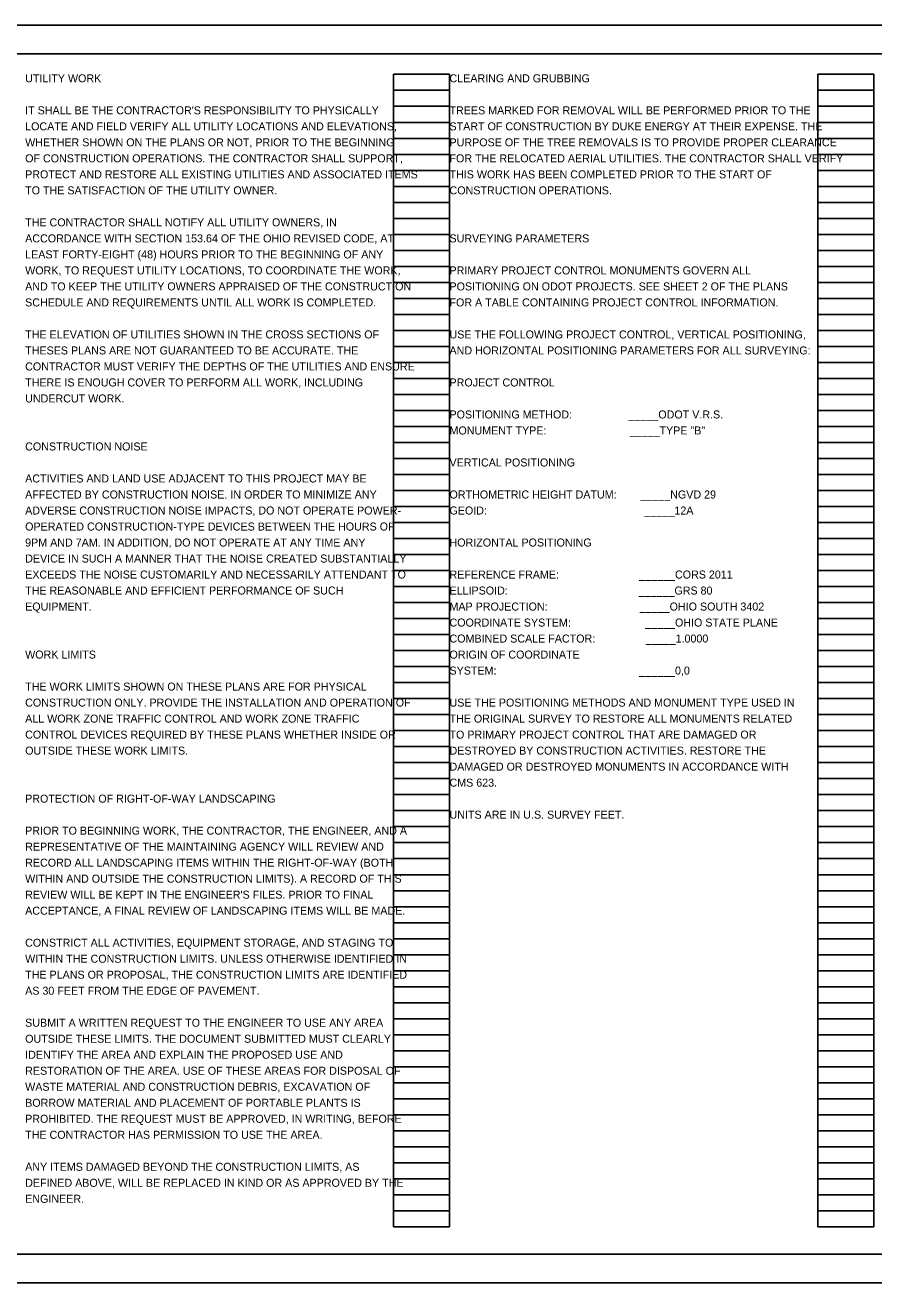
# Model space of a CAD drawing. Extents: x 0 to 50.1, y 0 to 22.
# Drawn here: x 9.82 to 24.66, y 0 to 22 of the extents above; entities that cross this region are included whole.
import ezdxf

# ---------------------------------------------------------------- set-up
doc = ezdxf.new("R2010")
doc.units = 0
for name, color, linetype in [('SH_Border', 7, 'Continuous'), ('SH_Cut_Line', 7, 'Continuous'), ('SH_Data', 7, 'Continuous'), ('SH_Text', 7, 'Continuous')]:
    doc.layers.add(name, color=color, linetype=linetype)

msp = doc.modelspace()

# ---------------------------------------------------------------- linework, layer by layer
at = {"layer": 'SH_Border'}
msp.add_lwpolyline([(1.5, 21.5), (33.5, 21.5), (33.5, 0.5), (1.5, 0.5)], close=True, dxfattribs=at)
at = {"layer": 'SH_Cut_Line'}
msp.add_lwpolyline([(0, 0), (34, 0), (34, 22), (0, 22)], close=True, dxfattribs=at)
at = {"layer": 'SH_Data'}
for p, q in [((16.26, 0.98), (16.26, 21.14)), ((16.26, 21.14), (17.24, 21.14)), ((17.24, 0.98), (17.24, 21.14)), ((23.68, 0.98), (23.68, 21.14)), ((23.68, 21.14), (24.66, 21.14)), ((24.66, 0.98), (24.66, 21.14)), ((16.26, 20.86), (17.24, 20.86)), ((23.68, 20.86), (24.66, 20.86)), ((16.26, 20.58), (17.24, 20.58)), ((23.68, 20.58), (24.66, 20.58)), ((16.26, 20.3), (17.24, 20.3)), ((23.68, 20.3), (24.66, 20.3)), ((16.26, 20.02), (17.24, 20.02)), ((23.68, 20.02), (24.66, 20.02)), ((16.26, 19.74), (17.24, 19.74)), ((23.68, 19.74), (24.66, 19.74)), ((16.26, 19.46), (17.24, 19.46)), ((23.68, 19.46), (24.66, 19.46)), ((16.26, 19.18), (17.24, 19.18)), ((23.68, 19.18), (24.66, 19.18)), ((16.26, 18.9), (17.24, 18.9)), ((23.68, 18.9), (24.66, 18.9)), ((16.26, 18.62), (17.24, 18.62)), ((23.68, 18.62), (24.66, 18.62)), ((16.26, 18.34), (17.24, 18.34)), ((23.68, 18.34), (24.66, 18.34)), ((16.26, 18.06), (17.24, 18.06)), ((23.68, 18.06), (24.66, 18.06)), ((16.26, 17.78), (17.24, 17.78)), ((23.68, 17.78), (24.66, 17.78)), ((16.26, 17.5), (17.24, 17.5)), ((23.68, 17.5), (24.66, 17.5)), ((16.26, 17.22), (17.24, 17.22)), ((23.68, 17.22), (24.66, 17.22)), ((16.26, 16.94), (17.24, 16.94)), ((23.68, 16.94), (24.66, 16.94)), ((16.26, 16.66), (17.24, 16.66)), ((23.68, 16.66), (24.66, 16.66)), ((16.26, 16.38), (17.24, 16.38)), ((23.68, 16.38), (24.66, 16.38)), ((16.26, 16.1), (17.24, 16.1)), ((23.68, 16.1), (24.66, 16.1)), ((16.26, 15.82), (17.24, 15.82)), ((23.68, 15.82), (24.66, 15.82)), ((16.26, 15.54), (17.24, 15.54)), ((23.68, 15.54), (24.66, 15.54)), ((16.26, 15.26), (17.24, 15.26)), ((23.68, 15.26), (24.66, 15.26)), ((16.26, 14.98), (17.24, 14.98)), ((23.68, 14.98), (24.66, 14.98)), ((16.26, 14.7), (17.24, 14.7)), ((23.68, 14.7), (24.66, 14.7)), ((16.26, 14.42), (17.24, 14.42)), ((23.68, 14.42), (24.66, 14.42)), ((16.26, 14.14), (17.24, 14.14)), ((23.68, 14.14), (24.66, 14.14)), ((16.26, 13.86), (17.24, 13.86)), ((23.68, 13.86), (24.66, 13.86)), ((16.26, 13.58), (17.24, 13.58)), ((23.68, 13.58), (24.66, 13.58)), ((16.26, 13.3), (17.24, 13.3)), ((23.68, 13.3), (24.66, 13.3)), ((16.26, 13.02), (17.24, 13.02)), ((23.68, 13.02), (24.66, 13.02)), ((16.26, 12.74), (17.24, 12.74)), ((23.68, 12.74), (24.66, 12.74)), ((16.26, 12.46), (17.24, 12.46)), ((23.68, 12.46), (24.66, 12.46)), ((16.26, 12.18), (17.24, 12.18)), ((23.68, 12.18), (24.66, 12.18)), ((16.26, 11.9), (17.24, 11.9)), ((23.68, 11.9), (24.66, 11.9)), ((16.26, 11.62), (17.24, 11.62)), ((23.68, 11.62), (24.66, 11.62)), ((16.26, 11.34), (17.24, 11.34)), ((23.68, 11.34), (24.66, 11.34)), ((16.26, 11.06), (17.24, 11.06)), ((23.68, 11.06), (24.66, 11.06)), ((16.26, 10.78), (17.24, 10.78)), ((23.68, 10.78), (24.66, 10.78)), ((16.26, 10.5), (17.24, 10.5)), ((23.68, 10.5), (24.66, 10.5)), ((16.26, 10.22), (17.24, 10.22)), ((23.68, 10.22), (24.66, 10.22)), ((16.26, 9.94), (17.24, 9.94)), ((23.68, 9.94), (24.66, 9.94)), ((16.26, 9.66), (17.24, 9.66)), ((23.68, 9.66), (24.66, 9.66)), ((16.26, 9.38), (17.24, 9.38)), ((23.68, 9.38), (24.66, 9.38)), ((16.26, 9.1), (17.24, 9.1)), ((23.68, 9.1), (24.66, 9.1)), ((16.26, 8.82), (17.24, 8.82)), ((23.68, 8.82), (24.66, 8.82)), ((16.26, 8.54), (17.24, 8.54)), ((23.68, 8.54), (24.66, 8.54)), ((16.26, 8.26), (17.24, 8.26)), ((23.68, 8.26), (24.66, 8.26)), ((16.26, 7.98), (17.24, 7.98)), ((23.68, 7.98), (24.66, 7.98)), ((16.26, 7.7), (17.24, 7.7)), ((23.68, 7.7), (24.66, 7.7)), ((16.26, 7.42), (17.24, 7.42)), ((23.68, 7.42), (24.66, 7.42)), ((16.26, 7.14), (17.24, 7.14)), ((23.68, 7.14), (24.66, 7.14)), ((16.26, 6.86), (17.24, 6.86)), ((23.68, 6.86), (24.66, 6.86)), ((16.26, 6.58), (17.24, 6.58)), ((23.68, 6.58), (24.66, 6.58)), ((16.26, 6.3), (17.24, 6.3)), ((23.68, 6.3), (24.66, 6.3)), ((16.26, 6.02), (17.24, 6.02)), ((23.68, 6.02), (24.66, 6.02)), ((16.26, 5.74), (17.24, 5.74)), ((23.68, 5.74), (24.66, 5.74)), ((16.26, 5.46), (17.24, 5.46)), ((23.68, 5.46), (24.66, 5.46)), ((16.26, 5.18), (17.24, 5.18)), ((23.68, 5.18), (24.66, 5.18)), ((16.26, 4.9), (17.24, 4.9)), ((23.68, 4.9), (24.66, 4.9)), ((16.26, 4.62), (17.24, 4.62)), ((23.68, 4.62), (24.66, 4.62)), ((16.26, 4.34), (17.24, 4.34)), ((23.68, 4.34), (24.66, 4.34)), ((16.26, 4.06), (17.24, 4.06)), ((23.68, 4.06), (24.66, 4.06)), ((16.26, 3.78), (17.24, 3.78)), ((23.68, 3.78), (24.66, 3.78)), ((16.26, 3.5), (17.24, 3.5)), ((23.68, 3.5), (24.66, 3.5)), ((16.26, 3.22), (17.24, 3.22)), ((23.68, 3.22), (24.66, 3.22)), ((16.26, 2.94), (17.24, 2.94)), ((23.68, 2.94), (24.66, 2.94)), ((16.26, 2.66), (17.24, 2.66)), ((23.68, 2.66), (24.66, 2.66)), ((16.26, 2.38), (17.24, 2.38)), ((23.68, 2.38), (24.66, 2.38)), ((16.26, 2.1), (17.24, 2.1)), ((23.68, 2.1), (24.66, 2.1)), ((16.26, 1.82), (17.24, 1.82)), ((23.68, 1.82), (24.66, 1.82)), ((16.26, 1.54), (17.24, 1.54)), ((23.68, 1.54), (24.66, 1.54)), ((16.26, 1.26), (17.24, 1.26)), ((23.68, 1.26), (24.66, 1.26)), ((16.26, 0.98), (17.24, 0.98)), ((23.68, 0.98), (24.66, 0.98))]:
    msp.add_line(p, q, dxfattribs=at)

# ---------------------------------------------------------------- texts
at = {"layer": 'SH_Text'}
for s, p in [('UTILITY WORK', (9.82, 21)), ('CLEARING AND GRUBBING', (17.24, 21)), ("IT SHALL BE THE CONTRACTOR'S RESPONSIBILITY TO PHYSICALLY ", (9.82, 20.44)), ('TREES MARKED FOR REMOVAL WILL BE PERFORMED PRIOR TO THE ', (17.24, 20.44)), ('LOCATE AND FIELD VERIFY ALL UTILITY LOCATIONS AND ELEVATIONS, ', (9.82, 20.16)), ('START OF CONSTRUCTION BY DUKE ENERGY AT THEIR EXPENSE. THE ', (17.24, 20.16)), ('WHETHER SHOWN ON THE PLANS OR NOT, PRIOR TO THE BEGINNING ', (9.82, 19.88)), ('PURPOSE OF THE TREE REMOVALS IS TO PROVIDE PROPER CLEARANCE ', (17.24, 19.88)), ('OF CONSTRUCTION OPERATIONS. THE CONTRACTOR SHALL SUPPORT, ', (9.82, 19.6)), ('FOR THE RELOCATED AERIAL UTILITIES. THE CONTRACTOR SHALL VERIFY ', (17.24, 19.6)), ('PROTECT AND RESTORE ALL EXISTING UTILITIES AND ASSOCIATED ITEMS ', (9.82, 19.32)), ('THIS WORK HAS BEEN COMPLETED PRIOR TO THE START OF ', (17.24, 19.32)), ('TO THE SATISFACTION OF THE UTILITY OWNER. ', (9.82, 19.04)), ('CONSTRUCTION OPERATIONS. ', (17.24, 19.04)), ('THE CONTRACTOR SHALL NOTIFY ALL UTILITY OWNERS, IN ', (9.82, 18.48)), ('ACCORDANCE WITH SECTION 153.64 OF THE OHIO REVISED CODE, AT ', (9.82, 18.2)), ('SURVEYING PARAMETERS', (17.24, 18.2)), ('LEAST FORTY-EIGHT (48) HOURS PRIOR TO THE BEGINNING OF ANY ', (9.82, 17.92)), ('WORK, TO REQUEST UTILITY LOCATIONS, TO COORDINATE THE WORK, ', (9.82, 17.64)), ('PRIMARY PROJECT CONTROL MONUMENTS GOVERN ALL', (17.24, 17.64)), ('AND TO KEEP THE UTILITY OWNERS APPRAISED OF THE CONSTRUCTION ', (9.82, 17.36)), ('POSITIONING ON ODOT PROJECTS. SEE SHEET 2 OF THE PLANS', (17.24, 17.36)), ('SCHEDULE AND REQUIREMENTS UNTIL ALL WORK IS COMPLETED. ', (9.82, 17.08)), ('FOR A TABLE CONTAINING PROJECT CONTROL INFORMATION.', (17.24, 17.08)), ('THE ELEVATION OF UTILITIES SHOWN IN THE CROSS SECTIONS OF ', (9.82, 16.52)), ('USE THE FOLLOWING PROJECT CONTROL, VERTICAL POSITIONING,', (17.24, 16.52)), ('THESES PLANS ARE NOT GUARANTEED TO BE ACCURATE. THE ', (9.82, 16.24)), ('AND HORIZONTAL POSITIONING PARAMETERS FOR ALL SURVEYING:', (17.24, 16.24)), ('CONTRACTOR MUST VERIFY THE DEPTHS OF THE UTILITIES AND ENSURE ', (9.82, 15.96)), ('THERE IS ENOUGH COVER TO PERFORM ALL WORK, INCLUDING ', (9.82, 15.68)), ('PROJECT CONTROL', (17.24, 15.68)), ('UNDERCUT WORK.', (9.82, 15.4)), ('POSITIONING METHOD:                   _____ODOT V.R.S.', (17.24, 15.12)), ('MONUMENT TYPE:                            _____TYPE "B"', (17.24, 14.84)), ('CONSTRUCTION NOISE', (9.82, 14.56)), ('VERTICAL POSITIONING', (17.24, 14.28)), ('ACTIVITIES AND LAND USE ADJACENT TO THIS PROJECT MAY BE ', (9.82, 14)), ('AFFECTED BY CONSTRUCTION NOISE. IN ORDER TO MINIMIZE ANY ', (9.82, 13.72)), ('ORTHOMETRIC HEIGHT DATUM:        _____NGVD 29', (17.24, 13.72)), ('ADVERSE CONSTRUCTION NOISE IMPACTS, DO NOT OPERATE POWER-', (9.82, 13.44)), ('GEOID:                                                     _____12A', (17.24, 13.44)), ('OPERATED CONSTRUCTION-TYPE DEVICES BETWEEN THE HOURS OF ', (9.82, 13.16)), ('9PM AND 7AM. IN ADDITION, DO NOT OPERATE AT ANY TIME ANY ', (9.82, 12.88)), ('HORIZONTAL POSITIONING', (17.24, 12.88)), ('DEVICE IN SUCH A MANNER THAT THE NOISE CREATED SUBSTANTIALLY ', (9.82, 12.6)), ('EXCEEDS THE NOISE CUSTOMARILY AND NECESSARILY ATTENDANT TO ', (9.82, 12.32)), ('REFERENCE FRAME:                           ______CORS 2011', (17.24, 12.32)), ('THE REASONABLE AND EFFICIENT PERFORMANCE OF SUCH ', (9.82, 12.04)), ('ELLIPSOID:                                            ______GRS 80', (17.24, 12.04)), ('EQUIPMENT.', (9.82, 11.76)), ('MAP PROJECTION:                               _____OHIO SOUTH 3402', (17.24, 11.76)), ('COORDINATE SYSTEM:                         _____OHIO STATE PLANE', (17.24, 11.48)), ('COMBINED SCALE FACTOR:                 _____1.0000', (17.24, 11.2)), ('WORK LIMITS', (9.82, 10.92)), ('ORIGIN OF COORDINATE', (17.24, 10.92)), ('SYSTEM:                                                ______0,0', (17.24, 10.64)), ('THE WORK LIMITS SHOWN ON THESE PLANS ARE FOR PHYSICAL ', (9.82, 10.36)), ('CONSTRUCTION ONLY. PROVIDE THE INSTALLATION AND OPERATION OF ', (9.82, 10.08)), ('USE THE POSITIONING METHODS AND MONUMENT TYPE USED IN', (17.24, 10.08)), ('ALL WORK ZONE TRAFFIC CONTROL AND WORK ZONE TRAFFIC ', (9.82, 9.8)), ('THE ORIGINAL SURVEY TO RESTORE ALL MONUMENTS RELATED', (17.24, 9.8)), ('CONTROL DEVICES REQUIRED BY THESE PLANS WHETHER INSIDE OR ', (9.82, 9.52)), ('TO PRIMARY PROJECT CONTROL THAT ARE DAMAGED OR', (17.24, 9.52)), ('OUTSIDE THESE WORK LIMITS.', (9.82, 9.24)), ('DESTROYED BY CONSTRUCTION ACTIVITIES. RESTORE THE', (17.24, 9.24)), ('DAMAGED OR DESTROYED MONUMENTS IN ACCORDANCE WITH', (17.24, 8.96)), ('CMS 623.', (17.24, 8.68)), ('PROTECTION OF RIGHT-OF-WAY LANDSCAPING', (9.82, 8.4)), ('UNITS ARE IN U.S. SURVEY FEET.', (17.24, 8.12)), ('PRIOR TO BEGINNING WORK, THE CONTRACTOR, THE ENGINEER, AND A ', (9.82, 7.84)), ('REPRESENTATIVE OF THE MAINTAINING AGENCY WILL REVIEW AND ', (9.82, 7.56)), ('RECORD ALL LANDSCAPING ITEMS WITHIN THE RIGHT-OF-WAY (BOTH ', (9.82, 7.28)), ('WITHIN AND OUTSIDE THE CONSTRUCTION LIMITS). A RECORD OF THIS ', (9.82, 7)), ("REVIEW WILL BE KEPT IN THE ENGINEER'S FILES. PRIOR TO FINAL ", (9.82, 6.72)), ('ACCEPTANCE, A FINAL REVIEW OF LANDSCAPING ITEMS WILL BE MADE.', (9.82, 6.44)), ('CONSTRICT ALL ACTIVITIES, EQUIPMENT STORAGE, AND STAGING TO ', (9.82, 5.88)), ('WITHIN THE CONSTRUCTION LIMITS. UNLESS OTHERWISE IDENTIFIED IN ', (9.82, 5.6)), ('THE PLANS OR PROPOSAL, THE CONSTRUCTION LIMITS ARE IDENTIFIED ', (9.82, 5.32)), ('AS 30 FEET FROM THE EDGE OF PAVEMENT.', (9.82, 5.04)), ('SUBMIT A WRITTEN REQUEST TO THE ENGINEER TO USE ANY AREA ', (9.82, 4.48)), ('OUTSIDE THESE LIMITS. THE DOCUMENT SUBMITTED MUST CLEARLY ', (9.82, 4.2)), ('IDENTIFY THE AREA AND EXPLAIN THE PROPOSED USE AND ', (9.82, 3.92)), ('RESTORATION OF THE AREA. USE OF THESE AREAS FOR DISPOSAL OF ', (9.82, 3.64)), ('WASTE MATERIAL AND CONSTRUCTION DEBRIS, EXCAVATION OF ', (9.82, 3.36)), ('BORROW MATERIAL AND PLACEMENT OF PORTABLE PLANTS IS ', (9.82, 3.08)), ('PROHIBITED. THE REQUEST MUST BE APPROVED, IN WRITING, BEFORE ', (9.82, 2.8)), ('THE CONTRACTOR HAS PERMISSION TO USE THE AREA.', (9.82, 2.52)), ('ANY ITEMS DAMAGED BEYOND THE CONSTRUCTION LIMITS, AS ', (9.82, 1.96)), ('DEFINED ABOVE, WILL BE REPLACED IN KIND OR AS APPROVED BY THE ', (9.82, 1.68)), ('ENGINEER.', (9.82, 1.4))]:
    msp.add_text(s, height=0.14, dxfattribs=at).set_placement(p)

doc.saveas('drawing.dxf')
